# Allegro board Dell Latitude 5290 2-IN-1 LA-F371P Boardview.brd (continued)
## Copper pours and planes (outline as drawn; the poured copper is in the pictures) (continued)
B+ on IN4 (solid shape): 85.17,77.71 85.17,72.99 83.08,70.91 83.08,57.98 82.52,57.42 80.21,57.42 79.48,58.15 79.48,61.15 79.5,61.18 79.5,61.41 80.29,62.19 80.29,65.44 79.5,66.23 79.5,68.82 80.62,69.94 80.62,72.86 82.4,74.64 82.4,77.54 82.98,78.12 84.76,78.12
B+ on VCC: 138.28,119.95 136.76,121.48 119.87,121.48 115.68,125.67 114.96,125.67 113.94,124.65 109.6,124.65 109.6,142.18 126.09,142.18 127.38,143.47 127.38,147.62 126.85,148.15 124.97,148.15 123.95,148.51 121.48,149.39 106.63,154.69 103.42,155.84 103.19,155.92 103.19,156.16 103.19,166.56 108.03,166.56 109.05,167.58 129.08,167.58 129.08,154.6 129.53,153.53 130.6,153.08 137.79,153.08 137.79,138.77 139.59,136.97 144.02,136.97 144.02,134.45 145.54,132.93 145.54,120.69 144.8,119.95
B+_USH on TOP (solid shape): 136.99,90.17 136.99,89.04 136.59,88.63 136.18,88.63 136.06,88.76 136.06,89.09 136.06,89.1 136.06,89.35 136.3,89.59 136.3,90.11 136.42,90.24 136.93,90.24
B+_USH on BOTTOM (solid shape): 126.03,93.16 126.03,92.06 125.73,91.76 123.79,91.76 123.75,91.8 123.75,92.34 123.86,92.44 124.28,92.44 125.07,93.23 125.96,93.23
BATT+ on TOP (solid shape): 143.33,119.95 143.42,119.9 143.41,119.79 143.36,119.61 143.44,119.45 143.45,119.43 143.7,119.18 143.7,116.4 143.51,116.21 141.67,116.21 141.1,115.64 139.27,115.64 139.15,115.76 139.15,117.11 140.02,117.98 140.91,117.98 141.48,118.56 141.48,118.73 142.01,118.73 142.34,119.06 142.01,119.39 141.48,119.39 141.48,119.95
CHG_ADP on BOTTOM (solid shape): 130.49,131.69 130.49,130.68 133.1,128.08 133.72,128.08 133.78,128.02 133.78,127.88 133.74,127.84 132.66,127.84 131.48,129.02 130.43,129.02 130.37,129.08 130.37,129.49 129.5,130.35 128.87,130.35 128.8,130.42 128.8,131.93 128.91,132.03 130.15,132.03
CHG_BGATE on TOP (solid shape): 138.94,117.79 138.94,115.79 138.81,115.66 138.53,115.66 138.37,115.83 138.37,117.79 138.43,117.86 138.87,117.86
CHG_BST1 on BOTTOM (solid shape): 133.79,126.43 133.79,126.3 133.73,126.24 131.57,126.24 131.44,126.11 131.44,125.48 131.38,125.41 130.81,125.41 130.75,125.48 130.75,126.37 130.87,126.49 133.73,126.49
CHG_BST2 on BOTTOM (solid shape): 135.7,124.91 135.7,123.06 135.45,122.81 135.45,122.24 134.56,122.24 134.56,123 134.68,123.13 135.19,123.13 135.45,123.38 135.45,124.91 135.51,124.97 135.64,124.97
CHG_DCIN on BOTTOM (solid shape): 132.41,131.17 132.41,130.65 133.74,129.31 133.79,129.31 134.09,129.02 134.09,128.22 134.02,128.16 133.79,128.16 131.39,130.56 130.84,130.56 130.62,130.77 130.62,131.12 130.82,131.32 132.26,131.32
CHG_LG1 on TOP (solid shape): 138.11,99.76 138.11,97.54 137.92,97.35 137.16,97.35 137.06,97.45 137.06,99.53 137.48,99.95 137.92,99.95
CHG_LG1 on IN2 (solid shape): 137.79,99.37 137.79,97.54 137.63,97.37 136.99,97.37 136.8,97.56 136.8,99.34 136.99,99.53 137.63,99.53
CHG_LG1 on IN2 (solid shape): 134.11,124.4 134.11,123.57 133.99,123.45 133.35,123.45 133.1,123.7 133.1,124.21 132.84,124.46 132.72,124.46 132.59,124.59 132.59,124.84 132.72,124.97 133.54,124.97
CHG_LG2 on TOP (solid shape): 126.11,123.89 126.11,122.87 125.86,122.62 125.86,121.6 125.73,121.48 125.22,121.48 125.22,121.48 125.05,121.48 124.98,121.55 124.98,122.89 125.41,123.32 125.41,123.83 125.6,124.02 125.98,124.02
CHG_LG2 on BOTTOM (solid shape): 134.49,124.91 134.49,123.95 133.99,123.45 133.86,123.45 133.79,123.51 133.79,123.64 134.24,124.08 134.24,124.91 134.3,124.97 134.43,124.97
CHG_LG2 on IN4 (solid shape): 126.3,123.83 126.3,122.81 126.68,122.43 126.68,121.79 126.49,121.6 126.11,121.6 125.6,122.11 125.6,123.83 125.79,124.02 126.11,124.02
CHG_LG2 on IN4 (solid shape): 134.3,123.89 134.3,123.76 133.73,123.19 133.73,122.94 133.48,122.68 133.16,122.68 132.72,123.13 132.72,123.45 132.97,123.7 133.73,123.7 133.99,123.95 134.24,123.95
CHG_LX1 on TOP (solid shape): 137.16,112.59 137.16,106.62 138.18,105.6 138.18,101.16 137.67,100.65 133.48,100.65 133.16,100.33 130.87,100.33 130.81,100.4 130.81,103.44 130.94,103.57 132.21,103.57 132.97,104.33 132.97,112.46 133.22,112.71 137.03,112.71
CHG_LX1 on BOTTOM (solid shape): 135.25,105.98 135.25,104.01 135.19,103.95 133.54,103.95 133.48,104.01 133.48,105.92 133.79,106.24 135,106.24
CHG_LX1 on BOTTOM (solid shape): 133.79,125.6 133.79,125.48 133.73,125.41 132.91,125.41 131.64,124.14 130.81,124.14 130.75,124.21 130.75,125.1 130.81,125.16 131.38,125.16 131.7,125.48 132.52,125.48 132.72,125.67 133.73,125.67
CHG_LX1 on IN2 (solid shape): 132.65,125.35 132.65,125.16 132.46,124.97 132.46,124.02 132.27,123.83 131.64,123.83 131.44,124.02 131.44,125.16 131.76,125.48 132.52,125.48
CHG_LX1 on IN2 (solid shape): 134.68,107 134.68,106.43 134.94,106.17 134.94,105.79 134.81,105.67 133.92,105.67 133.67,105.92 133.67,107.06 133.79,107.19 134.49,107.19
CHG_LX2 on TOP (solid shape): 131.83,120.97 131.83,118.05 131.57,117.79 130.3,117.79 129.67,117.16 129.67,109.03 128.91,108.27 124.08,108.27 123.83,108.52 123.83,112.59 124.84,113.6 124.84,120.21 125.35,120.72 129.67,120.72 130.18,121.22 131.57,121.22
CHG_LX2 on BOTTOM (solid shape): 128.4,117.22 128.4,115.57 128.21,115.38 126.94,115.38 126.62,115.7 126.62,117.22 126.68,117.29 128.33,117.29
CHG_LX2 on BOTTOM (solid shape): 134.9,124.92 134.9,123.66 134.18,122.94 134.18,122.24 133.29,122.24 133.29,123.06 133.48,123.26 133.99,123.26 134.67,123.94 134.67,124.89 134.75,124.97 134.85,124.97
CHG_LX2 on IN4 (solid shape): 131.25,118.56 131.25,118.3 130.87,117.92 129.67,117.92 129.48,118.11 129.48,118.87 129.6,119 130.81,119
CHG_LX2 on IN4 (solid shape): 134.81,123.83 134.81,123.13 134.87,123.06 134.87,122.56 134.75,122.43 133.99,122.43 133.86,122.56 133.86,123.13 134.62,123.89 134.75,123.89
CHG_UG1 on TOP (solid shape): 132.16,105.35 132.16,104.39 131.9,104.14 131,104.14 130.81,104.33 130.81,105.35 131.06,105.6 131.9,105.6
CHG_UG1 on BOTTOM (solid shape): 133.79,126.05 133.79,125.92 133.73,125.86 132.72,125.86 132.46,125.6 131.7,125.6 131.57,125.73 131.57,125.99 131.7,126.11 133.73,126.11
CHG_UG1 on IN2 (solid shape): 132.02,106.36 132.02,105.09 131.83,104.9 131.13,104.9 130.94,105.09 130.94,106.3 131.25,106.62 131.76,106.62
CHG_UG1 on IN2 (solid shape): 132.72,126.05 132.72,125.8 132.52,125.6 131.64,125.6 131.19,125.16 130.81,125.16 130.43,125.54 130.43,125.86 130.75,126.18 132.59,126.18
CHG_UG2 on TOP (solid shape): 131.7,117.16 131.7,116.02 131.57,115.89 130.56,115.89 130.3,116.14 130.3,117.03 130.56,117.29 131.57,117.29
CHG_UG2 on IN4 (solid shape): 131.7,117.41 131.7,116.02 131.64,115.95 130.68,115.95 130.56,116.08 130.56,117.16 131,117.6 131.51,117.6
CHG_UG2 on IN4 (solid shape): 136.08,123 136.08,122.56 135.95,122.43 135.19,122.43 135.06,122.56 135.06,123.13 135,123.19 135,123.83 135.06,123.89 135.19,123.89
CHG_VIN_20V on TOP (solid shape): 122.24,102.08 122.24,101.36 122.23,101.35 122.23,101 121.86,100.62 121.86,100.62 121.8,100.56 121.8,99.9 121.26,99.9 120.93,99.57 121.26,99.24 121.8,99.24 121.8,98.68 121.22,98.68 120.97,98.43 120.97,97.54 120.84,97.41 118.75,97.41 118.3,97.86 118.3,101.3 118.54,101.54 120.95,101.54 121.72,102.3 122.02,102.3
CORE_SW on BOTTOM (solid shape): 149.69,141.67 149.69,141.44 149.65,141.4 149.42,141.4 149.07,141.05 149.07,140.81 148.52,140.26 146.15,140.26 146.08,140.33 146.08,141.13 146.19,141.24 148.66,141.24 149.16,141.73 149.63,141.73
CPU_B+ on TOP (solid shape): 50.1,150.56 50.1,150.31 49.59,149.8 49.59,149.23 49.4,149.04 46.93,149.04 46.67,149.29 46.67,150.31 47.05,150.69 49.97,150.69
CPU_B+ on TOP (solid shape): 52.7,151.2 52.7,150.7 53.98,149.43 53.98,148.81 53.89,148.72 52.91,148.72 52.72,148.91 51.75,148.91 51.63,149.04 51.63,151.2 51.73,151.3 52.6,151.3
CPU_B+ on TOP (solid shape): 98.37,162.72 98.37,159.6 98.2,159.42 96.29,159.42 96.16,159.3 96.16,157.34 95.71,156.88 95.71,154.09 95.35,153.74 94.39,153.74 94.21,153.91 94.21,154.78 94.51,155.08 95.07,155.08 95.22,155.23 95.22,158.99 94.82,159.4 92.76,159.4 91.84,160.32 91.84,162.87 92.24,163.27 97.82,163.27
CPU_B+ on TOP (solid shape): 83.67,163.91 83.67,162.02 83.52,161.86 83.52,160.06 83.06,159.6 83.06,156.61 82.83,156.38 81.92,156.38 81.76,156.53 81.76,157.62 81.97,157.82 82.45,157.82 82.58,157.95 82.58,161.71 82.45,161.84 82.17,161.84 81.99,161.66 81.99,161.34 81.9,161.25 81.61,161.25 81.05,160.69 79.5,160.69 79.14,160.33 79.14,158.71 78.74,158.31 74.88,158.31 74.55,158.64 74.55,162.52 74.89,162.86 78.83,162.86 78.83,162.86 80.47,162.86 80.94,163.32 82.36,163.32 83.03,164 83.58,164
CPU_B+ on TOP (solid shape): 66.93,163.96 66.93,162.19 66.6,161.86 66.6,160.06 66.17,159.63 66.17,156.63 65.94,156.4 65.02,156.4 64.87,156.55 64.87,157.34 65.35,157.82 65.53,157.82 65.68,157.98 65.68,161.74 65.56,161.86 65.15,161.86 64.59,161.3 62.64,161.3 62.08,160.75 62.08,158.54 61.82,158.28 56.82,158.28 56.63,158.1 56.63,156.43 56.3,156.1 56.3,153.1 56.08,152.87 55.16,152.87 55.01,153.02 55.01,153.81 55.49,154.29 55.67,154.29 55.82,154.45 55.82,158.21 55.69,158.33 52.5,158.33 52.35,158.18 51.41,158.18 51.36,158.23 51.36,159.58 51.64,159.86 52.9,159.86 53.06,160.02 53.06,160.68 53.18,160.8 55.19,160.8 55.44,161.05 55.44,162.98 55.65,163.19 63.9,163.19 64,163.29 65.48,163.29 66.22,164.03 66.86,164.03
CPU_B+ on BOTTOM (solid shape): 52.69,151.07 52.69,149.43 52.3,149.04 47.04,149.04 46.85,149.23 46.85,150.56 46.95,150.66 49.84,150.66 50.38,151.2 52.57,151.2
CPU_B+ on BOTTOM (solid shape): 83.9,162.94 83.9,160.98 84.07,160.81 91.63,160.81 91.89,161.07 91.89,162.71 92.18,163.01 98.39,163.01 98.53,162.86 98.53,159.6 98.37,159.44 98.37,157.25 98.23,157.11 97.04,157.11 96.91,157.24 96.91,157.91 96.62,158.21 68.9,158.21 68.33,158.78 68.33,159.93 67.89,160.36 61.26,160.36 60.81,160.82 54.53,160.82 53.34,159.63 53.34,159.4 52.9,158.95 52.9,158.95 52.9,158.51 52.83,158.45 50.79,158.45 50.66,158.58 50.66,161.1 52.56,163.01 64.92,163.01 65.39,163.47 66.81,163.47 67.46,162.82 67.46,162.05 67.68,161.83 74.54,161.83 74.67,161.96 74.67,162.67 74.99,163 81.99,163 82.49,163.49 83.35,163.49
CPU_B+ on IN2 (solid shape): 57.05,158.94 57.05,156.85 56.81,156.61 55.77,156.61 55.51,156.86 55.51,158.32 56.29,159.09 56.9,159.09
CPU_B+ on IN3 (solid shape): outline of 1319 points within 47.88,149.04 98.41,163.5
CPU_B+ on VCC: 45.44,148.66 45.44,154.89 50.61,154.89 50.76,155.04 50.76,163.01 64.92,163.01 65.38,163.48 66.82,163.48 67.3,163.01 82.01,163.01 82.5,163.5 83.35,163.5 83.84,163.01 98.51,163.01 98.51,155.89 55.01,155.89 54.23,155.11 54.23,151.24 52.94,149.95 50.94,149.95 50,149.01 48.64,149.01 48.28,148.66
JUSBC1_GND on TOP (solid shape): 5.78,45.58 5.78,45.11 4.18,43.52 4.18,37.97 5.84,36.32 5.84,35.43 5.33,34.93 5.33,34.92 5.24,34.83 5.24,33.5 5.08,33.34 3.3,33.34 3.3,33.34 3.04,33.34 2.88,33.5 2.88,34.47 2.63,34.72 1.73,34.72 0.64,35.82 0.64,45.53 1.03,45.92 5.44,45.92
JUSBC1_GND on BOTTOM (solid shape): 6.08,45.68 6.08,45.05 5.82,44.79 4.65,44.79 4.3,44.45 4.3,36.95 4.55,36.7 5.82,36.7 6.1,36.43 6.1,35.84 5.81,35.55 0.25,35.55 0.25,44.93 1.28,45.95 5.82,45.95
JUSBC2_GND on TOP (solid shape): 9.65,33.09 9.65,31.43 9.46,31.24 7.81,31.24 7.28,30.72 6.18,30.72 5.61,30.15 4.86,30.15 3.88,29.17 3.88,23.66 5.78,21.77 5.78,21.26 5.55,21.03 2.11,21.03 2.11,21.02 1.02,21.02 0.64,21.4 0.64,32.45 1.17,32.99 7.49,32.99 7.91,33.4 9.33,33.4
JUSBC2_GND on BOTTOM (solid shape): 6.12,31.06 6.12,30.45 5.87,30.2 4.56,30.2 4.39,30.03 4.39,22.4 4.68,22.11 5.79,22.11 6.12,21.78 6.12,21.16 5.9,20.93 0.66,20.93 0.42,21.23 0.3,21.45 0.25,21.7 0.25,31.44 5.74,31.44
LCD_POWER_20V on TOP (solid shape): 34.92,33.72 34.92,32.58 35.05,32.45 35.81,32.45 36.2,32.83 39.24,32.83 40.13,31.94 40.13,29.66 39.88,29.4 36.7,29.4 36.45,29.66 36.2,29.66 35.43,30.42 31.62,30.42 31.24,30.8 31.24,31.18 30.99,31.43 29.59,31.43 29.21,31.82 29.21,33.59 29.59,33.97 34.67,33.97
LCD_POWER_20V on IN1 (solid shape): outline of 147 points within 81,65.55 84.23,80.43
LCD_POWER_20V on IN1 (solid shape): outline of 174 points within 38.53,27.55 55.24,32.57
LCD_POWER_20V on IN2 (solid shape): 82.75,67.35 82.75,66.36 82.52,66.13 81.69,66.13 81.61,66.21 81.61,67.35 81.94,67.68 82.42,67.68
LCD_POWER_20V on IN2 (solid shape): 66.45,64.61 66.45,41.04 55.68,30.27 55.64,30.31 55.6,30.37 55.61,30.45 55.29,30.97 55.16,30.38 55.2,30.31 55.18,30.23 55.12,30.03 55.19,29.84 55.21,29.8 54.97,29.55 54,29.55 53.96,29.59 52.95,29.59 52.45,30.09 52.45,32.02 64.06,43.63 64.06,62.07 62.97,63.16 62.97,64.48 63.42,64.94 66.12,64.94
LCD_POWER_20V on IN3 (solid shape): outline of 188 points within 63.25,62.93 82.75,68.06
LDO_1.0VA on TOP (solid shape): 132.14,143.7 132.14,143.13 132.08,143.07 131.57,143.07 130.73,142.23 129.89,142.23 129.82,142.16 129.82,141.29 129.78,141.25 129.14,141.25 129.08,141.31 129.08,142.23 129.54,142.69 130.43,142.69 131.51,143.77 132.08,143.77
LDO_IN on TOP (solid shape): 17.14,49.47 17.14,48.45 17.02,48.33 15.88,48.33 15.62,48.07 15.62,43.93 15.44,43.75 14.22,43.75 13.97,44.01 13.97,49.34 14.22,49.6 17.02,49.6
LDO_IN on IN4 (solid shape): 35.94,22.8 35.94,22.42 35.69,22.16 35.18,22.16 34.41,22.93 34.37,22.99 34.32,23.03 34.32,23.44 34.6,23.72 35.02,23.72
LED_SW on TOP (solid shape): 73.63,79 73.63,72.04 73.41,71.82 71.44,71.82 70.55,72.71 69.34,72.71 69.22,72.84 69.22,74 69.32,74.11 70.1,74.11 70.29,74.3 70.29,77.03 70.99,77.73 72.64,77.73 73,78.08 73,78.98 73.08,79.06 73.56,79.06
LX_1.0VA on TOP (solid shape): 127.13,144.59 130.18,144.59 130.43,144.34 130.43,143 130.3,142.88 128.65,142.88 128.46,142.69 128.46,141.29 128.4,141.23 127.83,141.23 127.64,141.42 127.64,141.99 127.13,142.5 127.13,143.07 125.98,144.21 125.98,145.1 126.05,145.16 126.56,145.16
LX_1.0VA on BOTTOM (solid shape): 128.4,143.32 128.4,142.31 128.27,142.18 127.38,142.18 127.25,142.31 127.25,143.32 127.38,143.45 128.27,143.45
LX_PRIM on TOP (solid shape): 48.44,145.02 48.44,144.42 48.36,144.34 47.37,144.34 46.93,143.89 46.93,143.26 46.86,143.19 44.13,143.19 44.07,143.26 44.07,144.4 44.32,144.65 46.3,144.65 46.75,145.1 48.37,145.1
LX_PRIM on BOTTOM (solid shape): 48.64,145.99 48.64,145.18 47.49,144.02 46.8,144.02 46.74,144.08 46.74,145.04 46.8,145.1 47.31,145.1 47.62,145.42 47.62,145.99 47.69,146.05 48.58,146.05
LX_VCCIO on TOP (solid shape): 122.68,127.89 122.68,127.19 122.62,127.13 121.86,127.13 121.42,126.69 121.42,125.94 121.08,125.6 118.55,125.6 118.36,125.8 118.36,127.57 118.75,127.95 122.62,127.95
LX_VCCIO on BOTTOM (solid shape): 121.35,127.26 121.35,125.8 121.22,125.67 120.46,125.67 120.21,125.92 120.21,127.26 120.33,127.38 121.22,127.38
PD1_LPS2 on TOP (solid shape): 22.33,38.29 23.27,38.29 23.9,37.66 23.9,34.91 23.77,34.79 21.31,34.79 20.07,36.03 18.34,36.03 17.83,36.54 17.83,39.31 18.08,39.56 21.06,39.56
PD2_LPS2 on TOP (solid shape): 25.22,28.46 25.22,26.13 24.16,25.06 23.34,25.06 22.73,24.45 22.35,24.45 21.84,23.94 18.92,23.94 18.67,24.2 18.67,24.63 18.69,24.65 18.69,26.96 18.75,27.01 20.45,27.01 22.17,28.74 24.94,28.74
PLL_COMP2 on BOTTOM (solid shape): 152.13,145.77 152.13,145.33 151.97,145.17 151.18,145.17 150.9,144.89 150.9,143.88 150.84,143.82 150.64,143.82 150.59,143.87 150.59,145.08 150.78,145.27 150.78,145.78 150.77,145.8 150.81,145.84 152.06,145.84
RING2 on BOTTOM (solid shape): 13.58,159.88 13.58,158.84 13.39,158.65 12.5,158.65 12.4,158.75 12.4,159.88 12.53,160.02 13.44,160.02
RING2 on BOTTOM (solid shape): 24.04,151.43 24.04,150.94 24.01,150.91 24.01,150.05 23.96,149.99 23.87,149.99 23.81,150.05 23.81,150.95 23.71,151.04 23.71,151.07 23.47,151.31 23.47,151.71 23.58,151.81 23.66,151.81
RING2 on IN3 (solid shape): 24.07,151.4 24.07,151.13 23.94,151 23.04,151 22.34,151.71 22.34,151.73 23,152.39 23.07,152.39
RING2 on IN3 (solid shape): 14.34,159.64 14.34,159.39 14.34,159.39 14.34,158.28 14.24,158.18 13.13,158.18 12.99,158.32 12.99,159.6 13.13,159.75 14.23,159.75
RING2_CONN on BOTTOM (solid shape): 12.76,164.78 12.76,161.16 13.24,160.69 13.24,160.26 13.15,160.17 12.23,160.17 11.75,160.66 11.75,164.85 11.84,164.94 12.61,164.94
SLEEVE on BOTTOM (solid shape): 15.81,159.88 15.81,159.03 15.43,158.65 13.95,158.65 13.83,158.77 13.83,159.95 13.85,159.98 15.71,159.98
SLEEVE on BOTTOM (solid shape): 24.51,152.01 24.51,150.95 24.43,150.87 24.43,150.05 24.37,149.98 24.25,149.98 24.2,150.04 24.2,151.42 23.84,151.78 23.84,152.11 23.93,152.2 24.32,152.2
SLEEVE on IN3 (solid shape): 16.51,160.38 16.51,159.49 16.36,159.35 14.88,159.35 14.67,159.56 14.67,160.3 14.8,160.43 16.46,160.43
SLEEVE on IN3 (solid shape): 24.91,152.2 24.91,151.56 24.63,151.27 24.35,151.27 23.43,152.19 23.43,152.36 23.96,152.89 24.22,152.89
SLEEVE_CONN on BOTTOM (solid shape): 15.37,163.64 15.37,160.66 14.86,160.15 13.84,160.15 13.78,160.21 13.78,160.67 13.89,160.78 13.97,160.78 14.31,161.12 14.31,163.6 14.48,163.77 15.24,163.77
SNUB_CHG1 on BOTTOM (solid shape): 135.32,102.36 135.32,100.59 134.94,100.2 133.79,100.2 133.41,100.59 133.41,102.43 133.48,102.49 135.19,102.49
SNUB_CHG2 on BOTTOM (solid shape): 128.4,120.59 128.4,118.94 128.27,118.81 126.68,118.81 126.62,118.87 126.62,120.72 126.87,120.97 128.02,120.97
SPK_-OUT-L+ on BOTTOM (solid shape): 66.72,12.81 66.72,11.71 66.68,11.67 65.56,11.67 65.41,11.82 65.41,12.7 65.54,12.83 66.7,12.83
SPK_-OUT-L+ on BOTTOM (solid shape): 29.54,148.03 29.54,147.92 29.55,147.92 29.55,147.66 29.47,147.58 28.49,147.58 28.39,147.48 27.17,147.48 27.11,147.54 27.11,147.63 27.17,147.69 28.26,147.69 28.64,148.06 29.51,148.06
SPK_-OUT-L+ on IN1 (solid shape): 29.58,148.17 29.58,147.66 29.5,147.58 28,147.58 27.84,147.41 27.52,147.41 27.25,147.67 27.25,148.02 27.5,148.27 29.48,148.27
SPK_-OUT-L+ on IN1 (solid shape): 66.23,12.49 66.23,11.56 66.18,11.51 65.55,11.51 65.47,11.59 65.47,12.14 64.81,12.8 64.81,12.91 65.17,13.27 65.45,13.27
SPK_-OUT-L- on BOTTOM (solid shape): 66.7,14.12 66.7,13.23 66.67,13.2 65.75,13.2 65.53,13.42 65.53,14.39 65.71,14.57 66.25,14.57
SPK_-OUT-L- on BOTTOM (solid shape): 29.62,147.4 29.62,146.98 29.56,146.91 28.68,146.91 28.55,147.04 28.03,147.04 27.99,147.08 27.16,147.08 27.11,147.13 27.11,147.23 27.17,147.29 28.21,147.29 28.44,147.29 28.58,147.43 29.6,147.43
SPK_-OUT-L- on IN1 (solid shape): 29.58,147.4 29.58,146.99 29.42,146.83 28.87,146.83 28.58,146.54 28.58,146.22 28.55,146.19 27.84,146.19 27.78,146.25 27.78,147.01 28.22,147.46 29.53,147.46
SPK_-OUT-L- on IN1 (solid shape): 66.28,14.8 66.28,13.59 66.13,13.44 65.67,13.44 65.52,13.59 65.52,14.49 65.14,14.87 65.14,14.99 65.51,15.36 65.58,15.42 65.66,15.42
SPK_-OUT-R+ on BOTTOM (solid shape): 66.7,16.71 67.52,16.71 67.56,16.66 67.56,15.85 67.49,15.77 66.09,15.77 65.82,16.04 65.82,16.83 65.93,16.94 66.47,16.94
SPK_-OUT-R+ on BOTTOM (solid shape): 28.48,146.14 30.08,146.14 30.19,146.04 30.19,145.75 30.1,145.67 28.62,145.67 28,146.28 27.16,146.28 27.11,146.33 27.11,146.43 27.17,146.49 28.14,146.49
SPK_-OUT-R+ on IN1 (solid shape): 30.09,146.08 30.09,144.99 29.84,144.74 29.21,144.74 29.05,144.91 29.05,146.09 29.13,146.18 30,146.18
SPK_-OUT-R+ on IN1 (solid shape): 66.61,17.66 66.61,15.93 66.46,15.77 66.09,15.77 65.85,16.02 65.85,17.7 65.91,17.76 66.51,17.76
SPK_-OUT-R- on BOTTOM (solid shape): 28.63,146.8 30.34,146.8 30.48,146.66 30.48,146.4 30.35,146.27 28.56,146.27 28.15,146.68 27.17,146.68 27.11,146.74 27.11,146.83 27.17,146.89 28.54,146.89
SPK_-OUT-R- on BOTTOM (solid shape): 67.6,19.47 67.6,16.93 67.56,16.9 67.03,16.9 66.94,16.99 66.94,17.94 66.41,18.46 66.41,19.51 66.54,19.64 67.43,19.64
SPK_-OUT-R- on IN1 (solid shape): 67.17,20.34 67.17,18.61 67.02,18.46 66.52,18.46 66.41,18.57 66.41,20.38 66.47,20.44 67.07,20.44
SPK_-OUT-R- on IN1 (solid shape): 30.98,146.89 30.98,145.5 30.96,145.47 30.28,145.47 30.23,145.52 30.23,146.18 30.11,146.3 29.49,146.3 29.4,146.39 29.4,146.64 29.81,147.05 29.81,147.05 29.88,147.12 30.75,147.12
SPK_L+ on TOP (solid shape): 81.56,5.01 81.56,4.61 81.12,4.17 80.07,4.17 79.68,4.56 79.68,5.11 79.77,5.2 81.37,5.2
SPK_L+ on BOTTOM (solid shape): 70.08,13.29 70.08,12.48 69.99,12.38 69.18,12.38 68.86,12.07 67.64,12.07 67.58,12.01 66.92,12.01 66.89,12.04 66.89,12.83 66.94,12.88 68.39,12.88 68.4,12.88 68.57,12.88 69.1,13.41 69.97,13.41
SPK_L+ on IN2 (solid shape): 71.19,13.31 71.19,12.5 71.08,12.39 69.72,12.39 69.53,12.58 69.53,13.36 69.59,13.42 71.08,13.42
SPK_L+ on IN2 (solid shape): 80.59,4.5 80.59,4.13 80.39,3.92 80.08,3.92 78.94,5.06 78.94,5.2 79.29,5.55 79.55,5.55
SPK_L- on TOP (solid shape): 82.17,5.02 82.17,4.43 82.17,4.29 82.05,4.17 82.05,3.34 81.99,3.28 81.39,3.28 81.31,3.36 81.31,4.21 81.72,4.62 81.72,5.02 81.85,5.15 82.04,5.15
SPK_L- on BOTTOM (solid shape): 70.43,14.83 70.43,13.97 70.14,13.68 68.91,13.68 68.43,13.19 66.92,13.19 66.88,13.23 66.88,13.96 66.95,14.03 67.76,14.03 67.86,13.93 68.31,13.93 68.68,14.3 68.68,14.36 69.27,14.95 70.32,14.95
SPK_L- on IN2 (solid shape): 71.19,14.61 71.19,13.79 71.08,13.69 69.72,13.69 69.53,13.88 69.53,14.66 69.61,14.74 71.06,14.74
SPK_L- on IN2 (solid shape): 81.77,4.75 81.77,3.2 81.72,3.15 81.04,3.15 80.87,3.32 80.87,4.9 81.07,5.1 81.42,5.1
SPK_R+ on TOP (solid shape): 82.76,5.01 82.76,3.38 82.72,3.33 82.22,3.33 82.17,3.38 82.17,4.11 82.31,4.25 82.31,5.05 82.37,5.12 82.65,5.12
SPK_R+ on BOTTOM (solid shape): 70.24,16.63 70.24,15.74 70.1,15.59 68.7,15.59 68.56,15.46 68.56,15.04 68.48,14.96 68.48,14.94 67.82,14.94 67.73,15.03 67.73,16.61 67.77,16.66 69.53,16.66 69.54,16.67 69.59,16.67 69.63,16.71 70.16,16.71
SPK_R+ on IN2 (solid shape): 71.34,16.55 71.34,15.74 71.24,15.63 69.88,15.63 69.69,15.82 69.69,16.6 69.77,16.68 71.22,16.68
SPK_R+ on IN2 (solid shape): 83.02,5.13 83.02,3.62 83.02,3.62 83.02,3.37 82.94,3.29 82.41,3.29 82.27,3.43 82.27,4.91 82.25,4.93 82.25,5.19 82.3,5.24 82.9,5.24
SPK_R- on TOP (solid shape): 83.36,5 83.36,4.61 83.68,4.29 83.68,3.42 83.57,3.31 83.04,3.31 82.94,3.41 82.94,5 83.04,5.1 83.26,5.1
SPK_R- on BOTTOM (solid shape): 69.47,18.75 70.05,18.75 70.23,18.57 70.23,17.17 70.04,16.98 69.54,16.98 69.48,16.92 67.85,16.92 67.81,16.97 67.81,17.66 67.81,17.73 67.81,17.74 67.81,17.84 67.87,17.91 68.55,17.91 68.69,18.04 68.69,18.58 68.87,18.76 69.47,18.76
SPK_R- on IN2 (solid shape): 71.28,18.14 71.28,17.32 71.18,17.22 69.81,17.22 69.63,17.41 69.63,18.19 69.71,18.27 71.15,18.27
SPK_R- on IN2 (solid shape): 84.09,5.05 84.09,3.44 84.01,3.37 83.24,3.37 83.13,3.47 83.13,4.97 83.31,5.14 84,5.14
SW_1.8VA on TOP (solid shape): 140.59,146.24 140.59,143.45 139.85,142.71 138.71,142.71 138.62,142.8 138.62,146.94 138.75,147.07 139.76,147.07
SW_1.8VA on BOTTOM (solid shape): 140.34,144.91 140.34,144.02 140.14,143.83 138.68,143.83 138.56,143.96 138.56,144.91 138.68,145.04 140.21,145.04
SW_1.8VU on TOP (solid shape): 108.63,95.32 108.63,94.12 108.97,93.79 109.98,93.79 110.24,93.54 110.24,92.78 110.11,92.65 106.3,92.65 106.17,92.78 106.17,93.55 107.31,94.7 107.31,95.29 107.44,95.42 108.54,95.42
N21618504 on TOP (solid shape): 119.44,117.92 119.44,116.08 121.03,114.49 122.56,114.49 122.68,114.37 122.68,113.86 121.41,112.59 117.73,112.59 117.6,112.71 117.6,115 119.06,116.46 119.06,117.92 119.19,118.05 119.32,118.05
N21618504 on BOTTOM (solid shape): 120.14,115.51 120.14,114.37 120.02,114.24 118.62,114.24 118.49,114.37 118.49,115.64 118.75,115.89 119.76,115.89
N21618541 on BOTTOM (solid shape): 120.08,118.18 120.08,116.21 119.95,116.08 118.55,116.08 118.55,116.91 119.06,116.91 119.38,117.22 119.38,118.24 120.02,118.24
N21622450 on TOP (solid shape): 119.95,117.1 119.95,116.71 120.9,115.76 122.17,115.76 122.3,115.64 122.3,114.87 122.17,114.75 121.16,114.75 119.57,116.33 119.57,117.1 119.7,117.22 119.82,117.22
N21624147 on TOP (solid shape): 46.99,158.82 46.99,155.2 45.99,154.19 45.99,153.89 45.92,153.82 45.8,153.82 45.72,153.9 45.72,155.45 45.15,156.02 42.55,156.02 42.35,156.21 42.35,158.43 42.93,159.01 46.8,159.01
N21624147 on BOTTOM (solid shape): 46.61,156.66 46.61,155.51 46.48,155.39 45.09,155.39 44.96,155.51 44.96,156.78 45.09,156.91 46.35,156.91
N21624512 on TOP (solid shape): 41.97,156.78 41.97,155.01 41.85,154.88 41.21,154.88 41.15,154.94 41.15,156.59 41.4,156.85 41.91,156.85
N21624514 on TOP (solid shape): 45.48,155.43 45.48,154.71 45.42,154.65 45.06,154.65 44.82,154.89 44.82,154.89 44.73,154.99 44.61,155.02 43.98,155.02 43.42,155.02 43.33,154.93 42.54,154.93 42.48,154.99 42.48,155.77 42.55,155.83 45.09,155.83
N21628480 on TOP (solid shape): 107.83,119.7 107.83,117.41 108.9,116.33 111.44,116.33 111.51,116.27 111.51,112.97 111.19,112.65 107.57,112.65 106.27,113.95 106.27,117.02 106.16,117.13 106.16,117.65 106.35,117.84 106.67,117.84 106.76,117.92 106.76,118.19 107.51,118.94 107.51,119.7 107.58,119.78 107.75,119.78
N21628480 on BOTTOM (solid shape): 107.95,119.06 107.95,117.29 107.7,117.03 106.37,117.03 106.11,117.29 106.11,118.88 106.43,119.19 107.82,119.19
N21628589 on TOP (solid shape): 108.45,124.91 109.66,124.91 109.92,124.65 109.92,122.62 108.52,121.22 108.52,119.25 108.39,119.13 108.14,119.13 108.01,119.25 108.01,121.72 107.63,122.1 107.63,123.52 107.44,123.72 107.44,125.01 107.52,125.09 108.26,125.09
N21637474 on TOP (solid shape): 108.33,118.49 108.33,118.05 108.71,117.67 111,117.67 111.06,117.6 111.06,116.71 111,116.65 108.84,116.65 108.01,117.48 108.01,118.49 108.08,118.56 108.27,118.56
N21637478 on TOP (solid shape): 112.46,117.6 112.46,115.83 112.33,115.7 111.82,115.7 111.76,115.76 111.76,117.6 111.82,117.67 112.39,117.67
N21803574 on TOP (solid shape): 40.01,21.4 40.01,20 39.75,19.75 38.73,19.75 38.61,19.88 38.61,21.4 38.73,21.53 39.88,21.53
N21803574 on BOTTOM (solid shape): 40.01,21.15 40.01,19.88 39.88,19.75 38.48,19.75 38.26,19.97 38.26,20.7 39.18,20.7 39.18,20.96 39.5,21.27 39.88,21.27
N22483924 on BOTTOM (solid shape): 144.4,139.7 144.4,137.19 144.25,137.03 143.45,137.03 143.38,137.1 143.38,139.84 143.5,139.95 144.15,139.95
N29436789 on TOP (solid shape): 92.27,159.48 92.27,156.36 92.1,156.2 90.96,156.2 90.75,156.4 90.75,158.33 90.77,158.35 90.77,159.5 90.92,159.65 92.09,159.65
N29436793 on TOP (solid shape): 85.09,159.55 85.09,157.93 85.34,157.67 87.53,157.67 87.71,157.49 87.71,152.95 87.6,152.85 83.69,152.85 83.19,153.35 83.19,159.5 83.34,159.65 84.99,159.65
N30656673 on TOP (solid shape): 119.98,144.9 119.98,143.06 122.2,140.84 122.83,140.84 122.96,140.71 122.96,140.08 122.96,140.07 122.96,139.71 122.68,139.43 117.25,139.43 117.09,139.59 117.09,142.53 117.94,143.38 118.83,143.38 119.66,144.2 119.66,144.9 119.72,144.97 119.91,144.97
N30656673 on BOTTOM (solid shape): 119.13,142.51 119.13,141.17 119.06,141.11 117.67,141.11 117.6,141.17 117.6,142.38 117.86,142.64 119,142.64
N30656795 on TOP (solid shape): 122.43,142.1 122.81,142.1 122.94,141.97 122.94,141.21 122.81,141.09 122.3,141.09 120.14,143.24 120.14,144.01 120.27,144.13 120.4,144.13
N30667395 on BOTTOM (solid shape): 48.64,156.66 48.64,155.64 48.39,155.39 46.86,155.39 46.8,155.45 46.8,156.85 46.86,156.91 48.39,156.91
N33626933 on TOP (solid shape): 32.52,103.27 32.52,101.18 32.44,101.1 31.69,101.1 31.55,101.24 31.55,103.26 31.63,103.34 32.45,103.34
N35110188 on TOP (solid shape): 22.38,49.27 22.38,48.38 22.3,48.3 18.49,48.3 18.31,48.48 18.31,49.19 18.54,49.42 22.24,49.42
N35110226 on TOP (solid shape): 24.1,47.89 24.1,46.98 23.77,46.65 23.77,45.1 23.57,44.9 23.57,44.41 23.44,44.29 22.2,44.29 21.39,45.1 20.93,45.1 20.73,45.3 20.73,45.89 21.06,46.22 21.69,46.22 22.61,47.13 22.61,47.89 22.81,48.1 23.9,48.1
N35114956 on TOP (solid shape): 18.57,32.2 18.57,30.75 18.41,30.6 17.63,30.6 16.87,31.36 15.77,31.36 15.47,31.66 15.47,32.32 15.67,32.53 16.59,32.53 16.84,32.78 17.98,32.78
N35624566 on BOTTOM (solid shape): 144.18,148.72 144.18,147.67 142.81,146.31 142.11,146.31 141.93,146.49 141.93,148.59 142.03,148.69 143.4,148.69 143.48,148.77 144.12,148.77
N36023370 on TOP (solid shape): 106.55,91.89 107.63,91.89 107.7,91.82 107.7,91 107.63,90.93 105.49,90.93 105.22,91.2 105.22,92.58 105.28,92.65 105.79,92.65
N36148115 on TOP (solid shape): 16.51,21.78 16.51,20.77 16.38,20.64 15.37,20.64 14.96,21.05 14.63,21.05 14.4,21.27 14.4,21.73 14.58,21.91 16.38,21.91
N36237197 on BOTTOM (solid shape): 21.91,146.43 21.91,146.33 21.86,146.28 20.58,146.28 20.3,146 20.3,144.55 20.23,144.49 19.57,144.49 19.57,145.12 19.54,145.12 19.54,146.44 19.59,146.49 21.86,146.49
N36239979 on BOTTOM (solid shape): 34.29,148.4 34.29,147.77 34.23,147.7 30.04,147.7 29.57,148.18 28.57,148.18 28.26,147.87 27.17,147.87 27.11,147.93 27.11,148.04 27.17,148.1 28.14,148.1 28.65,148.6 34.09,148.6
N36240770 on BOTTOM (solid shape): 28.59,145.54 31.5,145.54 31.66,145.38 31.78,145.38 31.8,145.35 32.69,145.35 32.87,145.53 32.87,145.81 32.94,145.89 33.97,145.89 34.02,145.84 34.02,144.57 33.98,144.5 33.96,144.43 33.43,143.89 32.07,143.89 31.88,144.08 31,144.08 30.39,144.69 30.39,144.93 30.21,145.11 28.7,145.11 27.98,145.84 27.17,145.84 27.11,145.89 27.11,146.03 27.17,146.09 28.04,146.09
N38000200 on TOP (solid shape): 24.37,49.46 24.37,48.85 24.03,48.5 23.19,48.5 22.9,48.79 22.9,49.46 23.14,49.7 24.13,49.7
N38000200 on TOP (solid shape): 28.96,45.4 28.96,44.52 28.83,44.39 28.57,44.39 28.45,44.52 28.45,44.77 28.32,44.9 27.56,44.9 27.43,45.02 27.43,45.28 27.56,45.4 28.32,45.4 28.45,45.53 28.83,45.53
N38000200 on IN2 (solid shape): 25.1,47.46 26.64,47.46 27.37,46.73 27.46,46.57 27.62,46.49 28.45,45.66 28.83,45.66 28.96,45.53 28.96,44.92 28.83,44.79 28.02,44.79 26.29,46.52 25.42,46.52 25.42,46.52 24.92,46.52 22.86,48.58 22.86,48.96 23.11,49.21 23.35,49.21
N38000331 on TOP (solid shape): 28.96,46.17 28.96,45.79 28.83,45.66 28.19,45.66 28.07,45.53 27.56,45.53 27.43,45.66 27.43,46.04 27.61,46.22 28.91,46.22
N38875212 on TOP (solid shape): 127.7,141.1 127.7,140.97 127.64,140.91 126.81,140.91 125.92,141.8 124.9,141.8 124.84,141.86 124.84,142.5 124.9,142.56 126.24,142.56
N40551930 on BOTTOM (solid shape): 28.04,127.37 28.04,126.98 27.94,126.88 27.7,126.88 27.64,126.9 27.58,126.9 27.53,126.9 27.47,126.88 27.28,126.88 27.2,126.96 27.2,127.37 27.09,127.48 27.09,127.64 26.84,127.89 26.35,127.89 26.24,128.01 26.24,128.26 26.34,128.36 27.05,128.36
N43524149 on TOP (solid shape): 37.67,41.82 37.67,41.78 37.89,41.78 38.3,41.37 38.3,38.98 37.93,38.61 36.94,38.61 36.86,38.7 36.86,41.01 36.67,41.2 36.67,41.37 36.4,41.64 36.4,42.03 36.6,42.23 37.26,42.23
N45337950 on TOP (solid shape): 137.32,135.96 137.32,134.47 137.22,134.37 136.47,134.37 136.24,134.6 136.24,135.09 136,135.33 136,136.02 136.15,136.17 137.1,136.17
N46285260 on TOP (solid shape): 81.04,81.07 81.04,78.22 81.34,77.91 82.28,77.91 82.44,78.07 82.44,78.6 82.6,78.77 83.07,78.77 83.18,78.66 83.18,76.97 83.02,76.81 81.46,76.81 81.06,76.41 80.08,76.41 79.91,76.58 79.91,80.85 80.27,81.21 80.9,81.21
N46645023 on TOP (solid shape): 68.2,159.58 68.2,157.95 68.45,157.7 70.64,157.7 70.82,157.52 70.82,152.97 70.71,152.87 66.8,152.87 66.29,153.38 66.29,159.53 66.45,159.68 68.1,159.68
N46645025 on TOP (solid shape): 74.05,160.54 74.05,158.52 73.81,158.28 72.31,158.28 72.16,158.43 72.16,158.9 71.86,159.21 70.75,159.21 70.6,159.36 70.6,160.53 70.78,160.71 73.89,160.71
N46647976 on TOP (solid shape): 103.73,157.57 103.73,155.01 103.56,154.83 102.59,154.83 102.46,154.95 102.46,157.62 102.62,157.77 103.53,157.77
N46647978 on TOP (solid shape): 97.74,156.83 97.74,155.21 98.81,154.14 98.81,147.49 98.73,147.41 94.92,147.41 94.84,147.49 94.84,151.47 95.83,152.47 95.83,156.78 95.99,156.94 97.64,156.94
N46648285 on TOP (solid shape): 60.95,155.9 60.95,150.99 60.67,150.71 56.63,150.71 56.43,150.92 56.43,156 56.58,156.15 60.71,156.15
N46648306 on TOP (solid shape): 55.65,150.79 55.65,149.25 55.32,148.92 54.36,148.92 54.15,149.12 54.15,149.66 53.8,150.01 53.8,150.88 53.95,151.03 55.41,151.03
N49571039 on TOP (solid shape): 125.22,144.46 125.79,143.89 125.79,143.26 124.9,143.26 124.9,143.89 124.59,144.21 124.59,145.1 125.22,145.1
N49816176 on TOP (solid shape): 37.04,36.81 37.06,36.76 37.08,36.72 37.08,34.61 36.83,34.36 33.15,34.36 32.89,34.61 32.89,36.77 33.15,37.02 36.83,37.02
N49817963 on TOP (solid shape): 30.99,31.05 30.99,29.02 30.86,28.89 30.26,28.89 30.22,28.93 28.59,28.93 28.55,28.89 26.92,28.89 26.67,29.15 26.67,30.8 26.8,30.93 27.81,30.93 28.07,31.18 30.86,31.18
N118152590 on BOTTOM (solid shape): 49.66,147.32 49.66,146.81 49.53,146.69 47.75,146.69 47.69,146.75 47.69,147.39 47.75,147.45 49.53,147.45

Small or netless copper shapes (teardrops, artwork), in the pictures only: 50 on TOP, 39 on BOTTOM, 11 on IN1, 1 on GND1, 40 on IN2, 1 on GND2, 2 on VCC, 32 on IN3, 1 on GND3, 45 on IN4

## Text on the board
Ref Des/Silkscreen Bottom: BS2 | BS1 | BS7 | CHA | BS3 | BS5 | BS4 | BS6 | CHB | RTC | uSIM | uSD
User.Comments: CR_UNNAMED_1 | LA-F371P | 2018-11-07 | 2017-11-07 | DAJ00 | crazy
Ref Des/Silkscreen Top: LA-F371P | Non-AR | TS4 | H5 | H10 | TS1 | H13 | H11 | TS2 | TS3 | 2230 SSD | WWAN | WLAN | LABEL | SSD | SPK | UFC | USH FPC | IR CAMERA | EDP | DOCKING FPC | WFC | BATT | FAN
BODY_CENTER: L7 | L8 | L9 | L10 | IN3 | IN4 | GND3 | BOT
User.39: trace Width | 2.7 / 2.4 | 72 ohm
User.40: FIGURE | SIZE | 4.0 | DRILL CHART: TOP to GND1 | ALL UNITS ARE IN MILS | TOLERANCE | +1.0/-1.0 | PLATED | QTY | 2439
User.41: FIGURE | SIZE | 4.0 | DRILL CHART: IN3 to GND3 | ALL UNITS ARE IN MILS | TOLERANCE | +1.0/-1.0 | PLATED | QTY | 284
User.42: FIGURE | SIZE | 4.0 | DRILL CHART: TOP to IN1 | ALL UNITS ARE IN MILS | TOLERANCE | +1.0/-1.0 | PLATED | QTY | 471
User.43: FIGURE | SIZE | 4.0 | DRILL CHART: IN1 to GND1 | ALL UNITS ARE IN MILS | TOLERANCE | +1.0/-1.0 | PLATED | QTY | 267
User.44: FIGURE | SIZE | 8.0 | 16.0 | 30.0 | 91.0 | 130.0 | 142.0 | 157.0 | 35.0 | 37.0 | 43.0 | 59.0 | 63.0 | 236.0 | 39.0x16.0 | 47.0x16.0 | 47.0x24.0 | 55.0x24.0 | 63.0x24.0 | 67.0x24.0 | 37.0x30.0 | DRILL CHART: TOP to BOTTOM | ALL UNITS ARE IN MILS | TOLERANCE | +3.0/-3.0 | +2.0/-2.0 | PLATED | NON-PLATED | QTY | 2349 | 24 | 10 | 6 | 4 | 1 | 2 | 3 | 8
User.45: stack-up setting ok | FIGURE | SIZE | 4.0 | DRILL CHART: GND3 to IN4 | ALL UNITS ARE IN MILS | DRILL CHART: IN3 to IN4 | DRILL CHART: IN3 to BOTTOM | DRILL CHART: TOP to IN2 | DRILL CHART: IN1 to IN2 | DRILL CHART: GND1 to IN2 | TOLERANCE | +1.0/-1.0 | PLATED | QTY | 402 | 443 | 1048 | 834 | 211 | 597 | 8.0 | DRILL CHART: GND3 to BOTTOM | DRILL CHART: IN4 to BOTTOM | DRILL CHART: GND1 to GND3 | +3.0/-3.0 | 2202 | 503 | 1067
